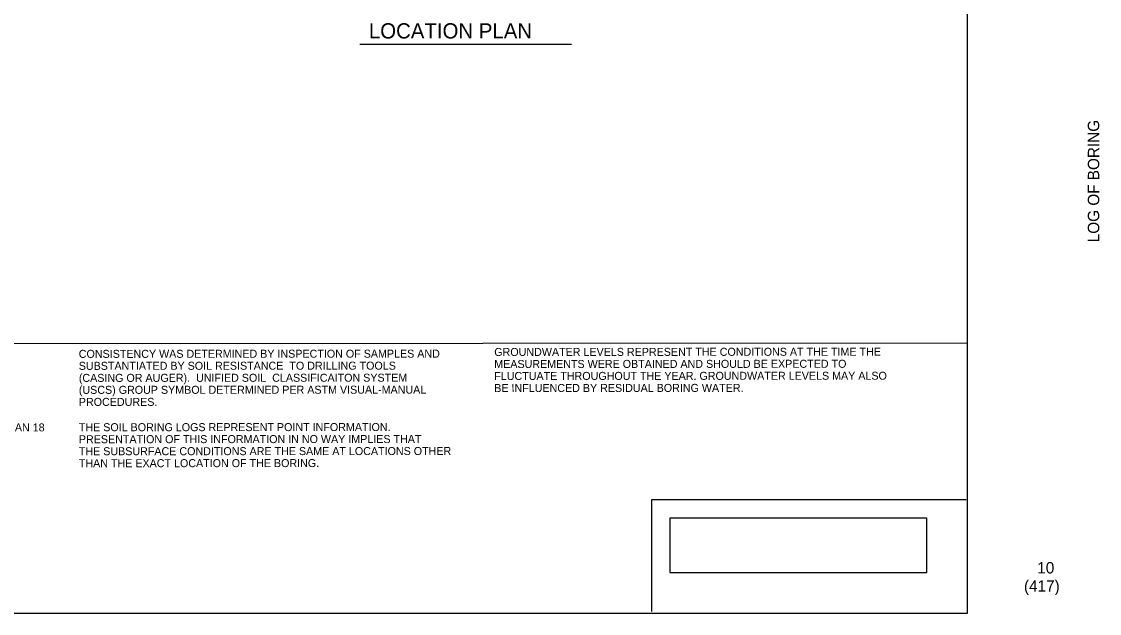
# Model space of a CAD drawing. Extents: x 19007.2 to 19038.3, y 21497.7 to 21516.9.
# Drawn here: x 19024.12 to 19038.25, y 21497.74 to 21505.5 of the extents above; entities that cross this region are included whole.
import ezdxf

# ---------------------------------------------------------------- set-up
doc = ezdxf.new("R2010")
doc.units = 0
for name, color, linetype in [('BORDER', 7, 'Continuous'), ('C-ANNO-TEXT', 7, 'Continuous'), ('G-ANNO-TTLB', 7, 'Continuous'), ('Level 1', 7, 'Continuous'), ('TYPICAL_TEXT_DIMEN_PR', 7, 'Continuous')]:
    doc.layers.add(name, color=color, linetype=linetype)

msp = doc.modelspace()

# ---------------------------------------------------------------- linework, layer by layer
at = {"layer": 'C-ANNO-TEXT'}
msp.add_line((19028.553, 21505.204), (19031.33, 21505.204), dxfattribs=at)
at = {"layer": 'G-ANNO-TTLB'}
for p, q in [((19036.503, 21499.228), (19032.375, 21499.228)), ((19032.375, 21499.228), (19032.375, 21497.763))]:
    msp.add_line(p, q, dxfattribs=at)
msp.add_lwpolyline([(19036.518, 21497.739), (19007.175, 21497.739), (19007.175, 21516.854), (19036.518, 21516.854)], close=True, dxfattribs=at)
at = {"layer": 'Level 1'}
msp.add_line((19007.175, 21501.269), (19036.525, 21501.289), dxfattribs=at)
at = {"layer": 'TYPICAL_TEXT_DIMEN_PR'}
msp.add_lwpolyline([(19032.618, 21498.277), (19035.986, 21498.277), (19035.986, 21498.99), (19032.618, 21498.99)], close=True, dxfattribs=at)

# ---------------------------------------------------------------- texts
at = {"layer": 'BORDER'}
for s, p in [('GROUNDWATER LEVELS REPRESENT THE CONDITIONS AT THE TIME THE ', (19030.315, 21501.115)), ('CONSISTENCY WAS DETERMINED BY INSPECTION OF SAMPLES AND ', (19024.867, 21501.09)), ('SUBSTANTIATED BY SOIL RESISTANCE  TO DRILLING TOOLS ', (19024.867, 21500.933)), ('MEASUREMENTS WERE OBTAINED AND SHOULD BE EXPECTED TO ', (19030.315, 21500.957)), ('(CASING OR AUGER).  UNIFIED SOIL  CLASSIFICAITON SYSTEM ', (19024.868, 21500.775)), ('FLUCTUATE THROUGHOUT THE YEAR. GROUNDWATER LEVELS MAY ALSO ', (19030.315, 21500.8)), ('(USCS) GROUP SYMBOL DETERMINED PER ASTM VISUAL-MANUAL ', (19024.868, 21500.618)), ('BE INFLUENCED BY RESIDUAL BORING WATER. ', (19030.315, 21500.642)), ('PROCEDURES.', (19024.868, 21500.46)), ('WHERE THE SAMPLER IS DRIVEN DISTANCES OTHER THAN 18 ', (19020.137, 21500.123)), ('THE SOIL BORING LOGS REPRESENT POINT INFORMATION. ', (19024.868, 21500.128)), ('PRESENTATION OF THIS INFORMATION IN NO WAY IMPLIES THAT ', (19024.868, 21499.971)), ('THE SUBSURFACE CONDITIONS ARE THE SAME AT LOCATIONS OTHER ', (19024.868, 21499.813)), ('THAN THE EXACT LOCATION OF THE BORING.', (19024.868, 21499.656))]:
    msp.add_text(s, height=0.10498, rotation=0.0399, dxfattribs=at).set_placement(p)
at = {"layer": 'C-ANNO-TEXT'}
msp.add_text('LOCATION PLAN', height=0.2, dxfattribs=at).set_placement((19028.671, 21505.278))
at = {"layer": 'G-ANNO-TTLB'}
msp.add_text('LOG OF BORING', height=0.15, rotation=90, dxfattribs=at).set_placement((19038.248, 21502.606))
for s, p in [('10', (19037.435, 21498.263)), ('(417)', (19037.261, 21498.024))]:
    msp.add_text(s, height=0.15, dxfattribs=at).set_placement(p)

doc.saveas('drawing.dxf')
